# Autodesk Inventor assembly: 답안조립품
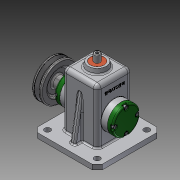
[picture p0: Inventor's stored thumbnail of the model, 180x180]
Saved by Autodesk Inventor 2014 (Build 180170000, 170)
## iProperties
Created: 2016-02
Part Number: 답안조립품
Document SubType Name: Assembly
Designer: J.H.CHAE
Author: J.H.CHAE
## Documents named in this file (16)
- C:\Users\Administrator\Desktop\460211V1031\답안조립품.iam
- C:\Users\Administrator\Desktop\460211V1031\1-본체.ipt
- C:\Users\Administrator\Desktop\460211V1031\V벨트풀리.ipt
- C:\Users\Administrator\Desktop\460211V1031\고정핀 1.2 x 10.ipt
- C:\Users\Administrator\Desktop\460211V1031\뒤커버.ipt
- C:\Users\Administrator\Desktop\460211V1031\링크.ipt
- C:\Users\Administrator\Desktop\460211V1031\멈춤나사 M3x8.ipt
- C:\Users\Administrator\Desktop\460211V1031\베어링 12 x 32 x 10.ipt
- C:\Users\Administrator\Desktop\460211V1031\볼트 M4 x 12.ipt
- C:\Users\Administrator\Desktop\460211V1031\부시.ipt
- C:\Users\Administrator\Desktop\460211V1031\슬라이드.ipt
- C:\Users\Administrator\Desktop\460211V1031\앞커버.ipt
- C:\Users\Administrator\Desktop\460211V1031\오일실 12 25 7.ipt
- C:\Users\Administrator\Desktop\460211V1031\키 4 x 4 x 10.ipt
- C:\Users\Administrator\Desktop\460211V1031\편심축.ipt
- C:\Users\Administrator\Desktop\460211V1031\핀 5 x 18.ipt
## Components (12 placed, 5 different names)
1. 1-본체:1
2. V벨트풀리:1
3. 고정핀 1.2 x 10:1
4. 핀 5 x 18:1
5. ISO 4762 M4 x 12:2
6. ISO 4762 M4 x 12:3
7. ISO 4762 M4 x 12:4
8. ISO 4762 M4 x 12:5
9. ISO 4762 M4 x 12:1
10. ISO 4762 M4 x 12:6
11. ISO 4762 M4 x 12:7
12. ISO 4762 M4 x 12:8
